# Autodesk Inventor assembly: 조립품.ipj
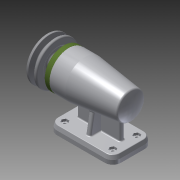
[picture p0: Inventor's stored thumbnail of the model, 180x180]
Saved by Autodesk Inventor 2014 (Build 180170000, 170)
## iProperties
Created: 2017-01
Part Number: 조립품.ipj
Document SubType Name: Assembly
Designer: owner
Author: owner
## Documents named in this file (11)
- C:\Users\owner\Desktop\470107V1004\조립품.ipj.iam
- C:\Users\owner\Desktop\470107V1004\본체.ipt
- C:\Users\owner\Desktop\470107V1004\베어링 6004.ipt
- C:\Users\owner\Desktop\470107V1004\축.ipt
- C:\Users\owner\Desktop\470107V1004\키 5 x 5 x 16.ipt
- C:\Users\owner\Desktop\470107V1004\베어링 51202.ipt
- C:\Users\owner\Desktop\470107V1004\볼트 M4 x 12.ipt
- C:\Users\owner\Desktop\470107V1004\어댑터슬리브.ipt
- C:\Users\owner\Desktop\470107V1004\V벨트풀리.ipt
- C:\Users\owner\Desktop\470107V1004\멈춤나사 M3x8.ipt
- C:\Users\owner\Desktop\470107V1004\커버.ipt
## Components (6 placed, 2 different names)
1. ISO 4762 M4 x 12:1
2. V벨트풀리:1
3. ISO 4762 M4 x 12:2
4. ISO 4762 M4 x 12:3
5. ISO 4762 M4 x 12:4
6. ISO 4762 M4 x 12:5
